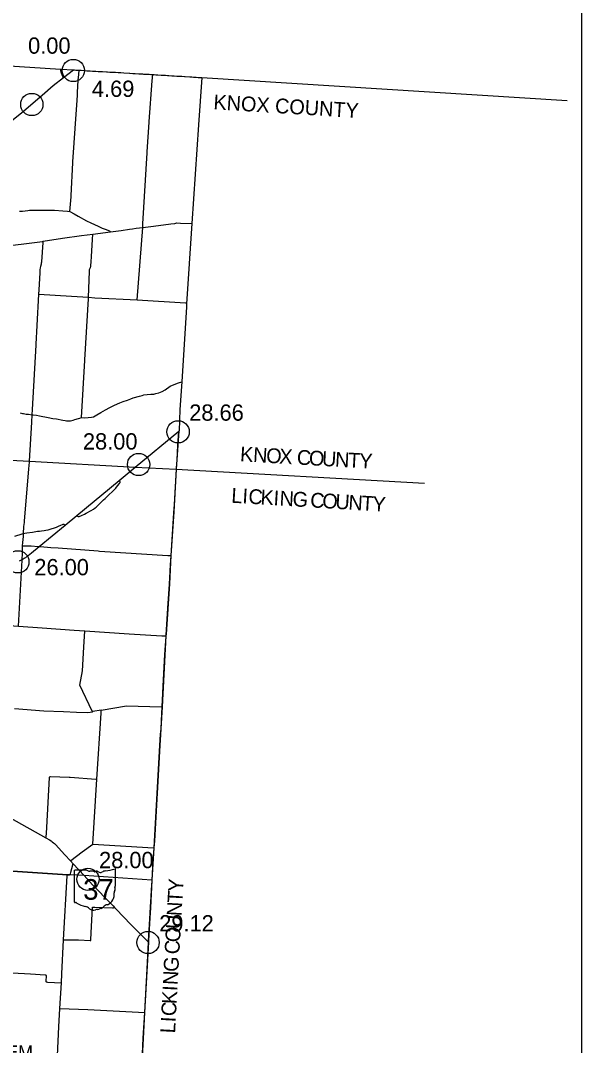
# Model space of a CAD drawing. Extents: x 1659811 to 1934326, y 644115 to 934867.
# Drawn here: x 1888004 to 1925846, y 790558 to 859763 of the extents above; entities that cross this region are included whole.
import ezdxf

# ---------------------------------------------------------------- set-up
doc = ezdxf.new("R2010")
doc.units = 0
for name, color, linetype in [('Default', 7, 'Continuous'), ('GM_X_Adjacent_County', 7, 'Continuous'), ('GM_X_Adjacent_County_Text', 7, 'Continuous'), ('GM_X_County', 7, 'Continuous'), ('GM_X_County_Road', 7, 'Continuous'), ('GM_X_State_Route', 7, 'Continuous'), ('GM_X_State_Shield', 7, 'Continuous'), ('GM_X_Township', 7, 'Continuous'), ('GM_X_Township_Road', 7, 'Continuous'), ('GM_X_Township_Text', 7, 'Continuous'), ('GM_X_US_Route', 7, 'Continuous'), ('SC_Scratch1', 7, 'Continuous')]:
    doc.layers.add(name, color=color, linetype=linetype)

msp = doc.modelspace()

# ---------------------------------------------------------------- linework, layer by layer
at = {"layer": 'Default'}
for centre in [(1891564, 856389), (1891564, 856389), (1888769, 854093), (1898635, 831992), (1895968, 829786), (1887823, 823212), (1892552, 801780), (1896611, 797510)]:
    msp.add_circle(centre, 750, dxfattribs=at)
at = {"layer": 'GM_X_Adjacent_County'}
for p, q in [((1900228, 855908), (1924873, 854361)), ((1898513, 829466), (1915254, 828516))]:
    msp.add_line(p, q, dxfattribs=at)
at = {"layer": 'GM_X_County'}
msp.add_lwpolyline([(1886895, 856734), (1890695, 856480), (1891588, 856432), (1891937, 856405), (1896895, 856116), (1900228, 855908), (1900008, 852727), (1899571, 846055), (1899210, 840637), (1899208, 840537), (1899202, 840435), (1898887, 835373), (1898754, 833509), (1898698, 832056), (1898677, 832037), (1898625, 831088), (1898557, 830092), (1898513, 829466), (1898352, 826597), (1898155, 823638), (1898045, 821739), (1897825, 818330), (1897815, 818218), (1897557, 813421), (1897406, 810815), (1897032, 804371), (1897004, 803896), (1896867, 801714), (1896762, 799856), (1896723, 799168), (1896641, 797645), (1896629, 797539), (1896376, 792790), (1896278, 791042), (1896113, 788102)], dxfattribs=at)
at = {"layer": 'GM_X_County_Road'}
for points in [[(1886387, 844458), (1889478, 844848), (1889539, 844855), (1890840, 845073), (1892109, 845243), (1892893, 845346), (1894066, 845501), (1894790, 845594), (1895349, 845664), (1895569, 845695), (1895814, 845736), (1896247, 845793), (1896967, 845887), (1898141, 846028), (1898411, 846062), (1898560, 846100), (1898798, 846088), (1899571, 846055)], [(1888604, 829939), (1888609, 830001), (1888760, 832637), (1888800, 833137), (1888812, 833505), (1889049, 837835), (1889053, 837918), (1889133, 839176), (1889247, 841285), (1889264, 841582), (1889332, 842735), (1889339, 842955), (1889347, 843044), (1889371, 843177), (1889414, 843329), (1889428, 843400), (1889436, 843472), (1889534, 844778), (1889539, 844855)], [(1887981, 833265), (1888133, 833232), (1888203, 833219), (1888385, 833194), (1888553, 833173), (1888800, 833137), (1888866, 833133), (1889085, 833106), (1889281, 833061), (1889870, 832955), (1890175, 832901), (1890421, 832859), (1890857, 832781), (1891011, 832754), (1891116, 832738), (1891228, 832726), (1891289, 832726), (1891379, 832736), (1891557, 832782), (1891660, 832813), (1891907, 832887), (1892010, 832918), (1892122, 832957), (1892327, 832934), (1892566, 832957), (1892784, 832982), (1892937, 833003), (1893157, 833131), (1893427, 833287), (1893731, 833483), (1894025, 833628), (1894350, 833781), (1894712, 833939), (1894934, 834036), (1895214, 834140), (1895437, 834225), (1895608, 834291), (1896021, 834405), (1896215, 834443), (1896330, 834491), (1896557, 834514), (1896797, 834537), (1896986, 834540), (1897122, 834582), (1897333, 834631), (1897563, 834720), (1897761, 834818), (1898107, 835064), (1898263, 835149), (1898656, 835291), (1898887, 835373)], [(1898531, 829465), (1898535, 829554), (1898563, 830092), (1898625, 831088), (1898677, 832037)], [(1888211, 825123), (1888238, 825608), (1888269, 825875), (1888275, 825951), (1888566, 829499), (1888604, 829939)], [(1897822, 818179), (1897829, 818255), (1897948, 820090), (1898048, 821704), (1898128, 823007), (1898166, 823650), (1898353, 826531), (1898388, 827089), (1898531, 829465)], [(1891807, 826349), (1891855, 826296), (1891892, 826275), (1891910, 826271), (1891947, 826267), (1891967, 826270), (1892112, 826338), (1892322, 826440), (1892434, 826497), (1892779, 826687), (1892926, 826772), (1893037, 826849), (1893103, 826910), (1893327, 827129), (1893595, 827398), (1893703, 827499), (1893960, 827731), (1894216, 827965), (1894365, 828110), (1894427, 828179), (1894548, 828334), (1894670, 828497), (1894687, 828515), (1894710, 828555), (1894718, 828575), (1894723, 828595), (1894722, 828618), (1894713, 828640), (1894693, 828679), (1894662, 828715)], [(1887621, 824941), (1888121, 825102), (1888211, 825123), (1888301, 825141), (1888421, 825162), (1888813, 825227), (1889047, 825270), (1889140, 825279), (1889289, 825293), (1889417, 825300), (1889589, 825323), (1889719, 825344), (1889858, 825376), (1890073, 825441), (1890297, 825503), (1890440, 825558), (1890572, 825616), (1890734, 825693), (1890836, 825744), (1890880, 825758), (1890902, 825760), (1890937, 825746), (1890980, 825715), (1891009, 825686)], [(1888119, 823374), (1888136, 823770), (1888147, 824305), (1888170, 824530), (1888198, 824915), (1888211, 825123)], [(1888147, 824305), (1888213, 824298), (1888717, 824283), (1889192, 824249), (1889265, 824243)], [(1889265, 824243), (1889344, 824238), (1890044, 824187), (1890551, 824150), (1893249, 823947), (1893321, 823942), (1897937, 823643), (1898048, 823639), (1898076, 823638), (1898114, 823638), (1898140, 823641), (1898166, 823650)], [(1887858, 818871), (1888113, 823336), (1888119, 823374)], [(1871277, 818480), (1872206, 818406), (1875525, 818156), (1880663, 817814), (1881619, 818131), (1884362, 819111), (1887858, 818871), (1889457, 818761), (1891623, 818604), (1892346, 818560), (1895326, 818344), (1897532, 818224), (1897769, 818211), (1897801, 818204), (1897822, 818179)], [(1897564, 813416), (1897624, 814812), (1897737, 816947), (1897822, 818179)], [(1896877, 801685), (1896878, 801713), (1896961, 803039), (1897015, 803890), (1897038, 804349), (1897401, 810812), (1897452, 811576), (1897482, 811930), (1897540, 812982), (1897564, 813416)], [(1896641, 797536), (1896646, 797601), (1896729, 799110), (1896778, 799931), (1896816, 800595), (1896842, 801059), (1896877, 801685)], [(1896288, 791046), (1896384, 792784), (1896550, 795738), (1896641, 797536)], [(1887442, 795472), (1888679, 795387), (1889657, 795329), (1889685, 795326), (1889702, 795320), (1889718, 795310), (1889731, 795291), (1889734, 795271), (1889715, 794891), (1889718, 794875), (1889726, 794861), (1889758, 794850), (1889831, 794843), (1890758, 794790)], [(1895958, 785443), (1895961, 785520), (1896121, 788099), (1896226, 789994), (1896288, 791046)]]:
    msp.add_lwpolyline(points, dxfattribs=at)
at = {"layer": 'GM_X_State_Route'}
for points in [[(1877908, 846019), (1878069, 846144), (1878991, 846854), (1880073, 847637), (1885437, 851504), (1886613, 852377), (1888074, 853536), (1889468, 854711), (1890217, 855366), (1890913, 855912), (1891583, 856425)], [(1883945, 807913), (1884008, 807879), (1884894, 807348), (1887358, 805901), (1889702, 804583), (1889965, 804433), (1890068, 804367), (1890146, 804309), (1890221, 804252), (1890297, 804190), (1890369, 804123), (1890999, 803432), (1891373, 803023), (1891553, 802825), (1892288, 802025), (1892862, 801410), (1894115, 800116), (1894249, 799980), (1894338, 799884), (1894447, 799772), (1895444, 798735), (1896641, 797536)]]:
    msp.add_lwpolyline(points, dxfattribs=at)
at = {"layer": 'GM_X_State_Shield'}
for p, q in [((1891630, 802365), (1891630, 800251)), ((1891630, 802365), (1891630, 800251)), ((1892472, 802401), (1891657, 802401)), ((1892472, 802401), (1891657, 802401)), ((1894414, 801348), (1894414, 802453)), ((1894414, 801348), (1894414, 802453)), ((1894414, 801348), (1894414, 801348)), ((1894414, 801348), (1894414, 801348))]:
    msp.add_line(p, q, dxfattribs=at)
for centre, radius, start, end in [((1891661, 802369), 32.3, 98.1301, 188.1301), ((1891661, 802369), 32.3, 98.1301, 188.1301), ((1892667, 802646), 313, 231.61951, 271.11188), ((1892667, 802646), 313, 231.61951, 271.11188), ((1892770, 801215), 1123, 80.48669, 94.98827), ((1892770, 801215), 1123, 80.48669, 94.98827), ((1893025, 802380), 90.3, 219.79206, 297.10237), ((1893025, 802380), 90.3, 219.79206, 297.10237), ((1893158, 802136), 188, 54.46668, 119.14113), ((1893158, 802136), 188, 54.46668, 119.14113), ((1893400, 802471), 226, 233.85621, 294.82819), ((1893400, 802471), 226, 233.85621, 294.82819), ((1893799, 801756), 594, 97.34618, 120.76885), ((1893799, 801756), 594, 97.34618, 120.76885), ((1893422, 805282), 2953, 275.84447, 288.90645), ((1893422, 805282), 2953, 275.84447, 288.90645), ((1894383, 802458), 31, 351.86209, 97.738), ((1894383, 802458), 31, 351.86209, 97.738), ((1893587, 800745), 739, 292.30889, 8.98584), ((1893587, 800745), 739, 292.30889, 8.98584), ((1894525, 800885), 210, 136.8065, 186.92959), ((1894525, 800885), 210, 136.8065, 186.92959), ((1894407, 801267), 48, 107.94398, 210.33697), ((1894407, 801267), 48, 107.94398, 210.33697), ((1894102, 801127), 288, 340.03296, 23.64957), ((1894102, 801127), 288, 340.03296, 23.64957), ((1894381, 801344), 33.2, 289.60381, 7.73413), ((1894381, 801344), 33.2, 289.60381, 7.73413), ((1891662, 800247), 32.5, 171.95839, 258.30661), ((1891662, 800247), 32.5, 171.95839, 258.30661), ((1891667, 800463), 248, 267.33899, 280.60386), ((1891667, 800463), 248, 267.33899, 280.60386), ((1891717, 800129), 89.5, 29.74838, 93.27175), ((1891717, 800129), 89.5, 29.74838, 93.27175), ((1892848, 802028), 2132, 240.41292, 257.1985), ((1892848, 802028), 2132, 240.41292, 257.1985), ((1893899, 799658), 404, 94.40312, 142.57675), ((1893899, 799658), 404, 94.40312, 142.57675), ((1892212, 799302), 667, 47.18416, 75.83597), ((1892212, 799302), 667, 47.18416, 75.83597), ((1892934, 800119), 423, 230.70037, 286.29184), ((1892934, 800119), 423, 230.70037, 286.29184), ((1893178, 799388), 348, 85.69512, 111.20995), ((1893178, 799388), 348, 85.69512, 111.20995), ((1893209, 799961), 226, 268.77702, 315.54927), ((1893209, 799961), 226, 268.77702, 315.54927), ((1893413, 799756), 63.5, 65.75173, 132.64842), ((1893413, 799756), 63.5, 65.75173, 132.64842), ((1893386, 800047), 239, 282.87319, 323.27711), ((1893386, 800047), 239, 282.87319, 323.27711)]:
    msp.add_arc(centre, radius, start, end, dxfattribs=at)
at = {"layer": 'GM_X_Township'}
for points in [[(1885186, 830186), (1888609, 830001), (1895732, 829600), (1898513, 829466)], [(1896867, 801714), (1892288, 802025), (1891297, 802083), (1891221, 802088), (1891165, 802089), (1883392, 802588)]]:
    msp.add_lwpolyline(points, dxfattribs=at)
at = {"layer": 'GM_X_Township_Road'}
for points in [[(1890913, 855912), (1890862, 855972), (1890828, 856035), (1890756, 856263), (1890718, 856382), (1890717, 856500)], [(1891583, 856425), (1891639, 856423), (1891746, 856417), (1891965, 856405)], [(1891854, 854895), (1891886, 855736), (1891944, 856127), (1891965, 856405)], [(1891965, 856405), (1892090, 856398), (1892301, 856385), (1892481, 856374), (1892856, 856351), (1893019, 856342), (1893232, 856329), (1893543, 856312), (1893805, 856297), (1893879, 856293), (1894034, 856284), (1894263, 856272), (1894410, 856264), (1894590, 856253), (1894770, 856241), (1894983, 856228), (1895376, 856205), (1895572, 856194), (1895703, 856186), (1895981, 856169), (1896095, 856161), (1896177, 856156), (1896242, 856153), (1896308, 856149), (1896553, 856136), (1896684, 856128), (1896799, 856122), (1896913, 856115), (1896923, 856115)], [(1896693, 852936), (1896693, 852946), (1896876, 855684), (1896923, 856115)], [(1896923, 856115), (1897028, 856108), (1897142, 856101), (1897208, 856097), (1897503, 856079), (1897601, 856072), (1897699, 856066), (1897780, 856061), (1897911, 856054), (1898222, 856035), (1898370, 856027), (1898550, 856015), (1898713, 856004), (1898778, 856000), (1898893, 855993), (1899057, 855983), (1899416, 855960), (1899563, 855950), (1899678, 855942), (1899792, 855935), (1899988, 855922), (1900186, 855910)], [(1891340, 846864), (1891414, 847853), (1891419, 847939), (1891537, 850153), (1891540, 850214), (1891785, 853757), (1891824, 854360), (1891848, 854742), (1891854, 854895)], [(1896247, 845793), (1896262, 846026), (1896550, 850831), (1896553, 850892), (1896690, 852894), (1896692, 852927), (1896693, 852936)], [(1887931, 846886), (1888141, 846889), (1888497, 846936), (1888601, 846948), (1888952, 846957), (1889403, 846957), (1889669, 846954), (1890015, 846956), (1890296, 846958), (1890853, 846915), (1891169, 846885), (1891340, 846864)], [(1891340, 846864), (1891616, 846711), (1891890, 846553), (1892461, 846246), (1892758, 846106), (1893234, 845882), (1893382, 845812), (1893507, 845752), (1893710, 845669), (1893997, 845564), (1894023, 845549), (1894046, 845529), (1894066, 845501)], [(1895863, 840910), (1896247, 845793)], [(1892122, 832957), (1892339, 836806), (1892341, 836860), (1892582, 840972), (1892585, 841036), (1892586, 841074), (1892651, 842825), (1892652, 842854), (1892658, 842912), (1892664, 842941), (1892680, 842997), (1892719, 843085), (1892728, 843106), (1892742, 843149), (1892749, 843194), (1892750, 843216), (1892770, 843468), (1892794, 843834), (1892869, 844984), (1892893, 845346)], [(1889247, 841285), (1891451, 841156), (1892586, 841074), (1893022, 841042), (1895863, 840910), (1899143, 840698), (1899170, 840695), (1899188, 840685), (1899198, 840677), (1899202, 840668), (1899210, 840637), (1899208, 840537)], [(1892877, 813100), (1892856, 813096), (1892847, 813127), (1892013, 814894), (1892187, 815844), (1892275, 817450), (1892346, 818560)], [(1887597, 813309), (1889585, 813162), (1890912, 813114), (1891786, 813054), (1892545, 813045), (1892856, 813096)], [(1891373, 803023), (1891387, 803039), (1891405, 803057), (1892171, 803626), (1892889, 804151), (1893142, 808538), (1893444, 812998), (1893450, 813114), (1893446, 813209)], [(1893446, 813209), (1892877, 813100)], [(1893446, 813209), (1895152, 813500), (1896723, 813446), (1897564, 813416)], [(1889702, 804583), (1889716, 804612), (1889727, 804647), (1889746, 804884), (1889770, 805286), (1889966, 808657), (1889971, 808727), (1890002, 808726), (1890019, 808725)], [(1890019, 808725), (1891290, 808671), (1891349, 808669), (1893087, 808542), (1893142, 808538)], [(1892889, 804151), (1896968, 803896), (1897015, 803890)], [(1891312, 802088), (1891337, 802094), (1891347, 802102), (1891354, 802110), (1891365, 802128), (1891402, 802264), (1891525, 802755), (1891537, 802794), (1891544, 802811), (1891553, 802825)], [(1883392, 802588), (1891165, 802089)], [(1890439, 788430), (1890599, 791825), (1890663, 793067), (1890758, 794790), (1890789, 795400), (1890905, 797697), (1891157, 802023), (1891165, 802089), (1891207, 802088)], [(1891207, 802088), (1891221, 802088), (1891297, 802083), (1891312, 802088)], [(1890905, 797697), (1891923, 797682), (1892705, 797649), (1892735, 797650), (1892749, 797657), (1892754, 797681), (1892755, 797718), (1892849, 799904), (1892999, 799898)], [(1892999, 799898), (1893021, 799897), (1894207, 799861), (1894280, 799859), (1894312, 799865), (1894338, 799884)], [(1890663, 793067), (1892550, 792979), (1896384, 792784)]]:
    msp.add_lwpolyline(points, dxfattribs=at)
at = {"layer": 'GM_X_US_Route'}
msp.add_lwpolyline([(1887941, 823279), (1888119, 823374), (1888248, 823452), (1888302, 823484), (1888354, 823517), (1888407, 823552), (1888458, 823588), (1888528, 823642), (1888751, 823815), (1889265, 824243), (1891009, 825686), (1891807, 826349), (1894662, 828715), (1895732, 829600), (1898677, 832037), (1898698, 832056)], dxfattribs=at)
at = {"layer": 'SC_Scratch1'}
msp.add_lwpolyline([(1729596, 899996), (1925846, 899996), (1925846, 765496), (1729596, 765496)], close=True, dxfattribs=at)

# ---------------------------------------------------------------- texts
at = {"layer": 'Default'}
for s, p in [('0.00', (1888514, 857520)), ('4.69', (1892821, 854605)), ('28.66', (1899385, 832742)), ('28.00', (1892214, 830795)), ('26.00', (1888935, 822305)), ('28.00', (1893302, 802530)), ('29.12', (1897361, 798260))]:
    msp.add_text(s, height=1100, dxfattribs=at).set_placement(p)
at = {"layer": 'GM_X_Adjacent_County_Text'}
for s, rotation, p in [('KNOX COUNTY', 356.53125, (1900997, 853771)), ('K', 356.69608, (1902793, 830006)), ('N', 356.69608, (1903674, 829955)), ('O', 356.69612, (1904555, 829905)), ('X', 356.69784, (1905437, 829854)), ('C', 356.74947, (1906624, 829785)), ('O', 356.8064, (1907439, 829739)), ('U', 356.86128, (1908321, 829690)), ('N', 356.87235, (1909203, 829641)), ('T', 356.87237, (1910084, 829593)), ('Y', 356.87237, (1910830, 829553)), ('L', 356.73283, (1902204, 827206)), ('I', 356.71388, (1902950, 827163)), ('C', 356.68679, (1903356, 827140)), ('K', 356.65754, (1904170, 827093)), ('I', 356.64879, (1905051, 827041)), ('N', 356.64663, (1905457, 827018)), ('G', 356.61826, (1906338, 826966)), ('C', 356.58516, (1907524, 826896)), ('O', 356.56641, (1908338, 826847)), ('U', 356.55931, (1909219, 826794)), ('N', 356.55604, (1910100, 826741)), ('T', 356.55678, (1910981, 826688)), ('Y', 356.55678, (1911726, 826643)), ('Y', 86.76654, (1898954, 800905)), ('T', 86.76739, (1898911, 800158)), ('N', 86.76746, (1898862, 799275)), ('U', 86.76017, (1898812, 798392)), ('O', 86.73209, (1898761, 797508)), ('C', 86.44872, (1898710, 796690)), ('G', 86.94188, (1898647, 795506)), ('N', 86.97466, (1898600, 794623)), ('I', 86.97386, (1898579, 794215)), ('K', 86.97892, (1898532, 793332)), ('C', 86.98, (1898489, 792519)), ('I', 86.98081, (1898468, 792110)), ('L', 86.97984, (1898428, 791363))]:
    msp.add_text(s, height=1000, rotation=rotation, dxfattribs=at).set_placement(p)
at = {"layer": 'GM_X_State_Shield'}
msp.add_text('37', height=1392.2, dxfattribs=at).set_placement((1892230, 800400))
msp.add_text('37', height=1392.2, dxfattribs=at).set_placement((1892230, 800400))
at = {"layer": 'GM_X_Township_Text'}
msp.add_text('HARLEM', height=900, rotation=0.00001, dxfattribs=at).set_placement((1883833, 789665))

doc.saveas('drawing.dxf')
